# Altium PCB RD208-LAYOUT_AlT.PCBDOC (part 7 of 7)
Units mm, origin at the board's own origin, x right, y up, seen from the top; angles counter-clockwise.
Board outline 240 x 150 mm, 6 copper layers (TOP, Mid-Layer 1, Mid-Layer 2, Mid-Layer 3, Mid-Layer 4, BOTTOM), stack 1.422 mm thick; 773 components, 409 nets, 3936 pads, 97 vias.
Unrouted connection lines stored in the file: 1.
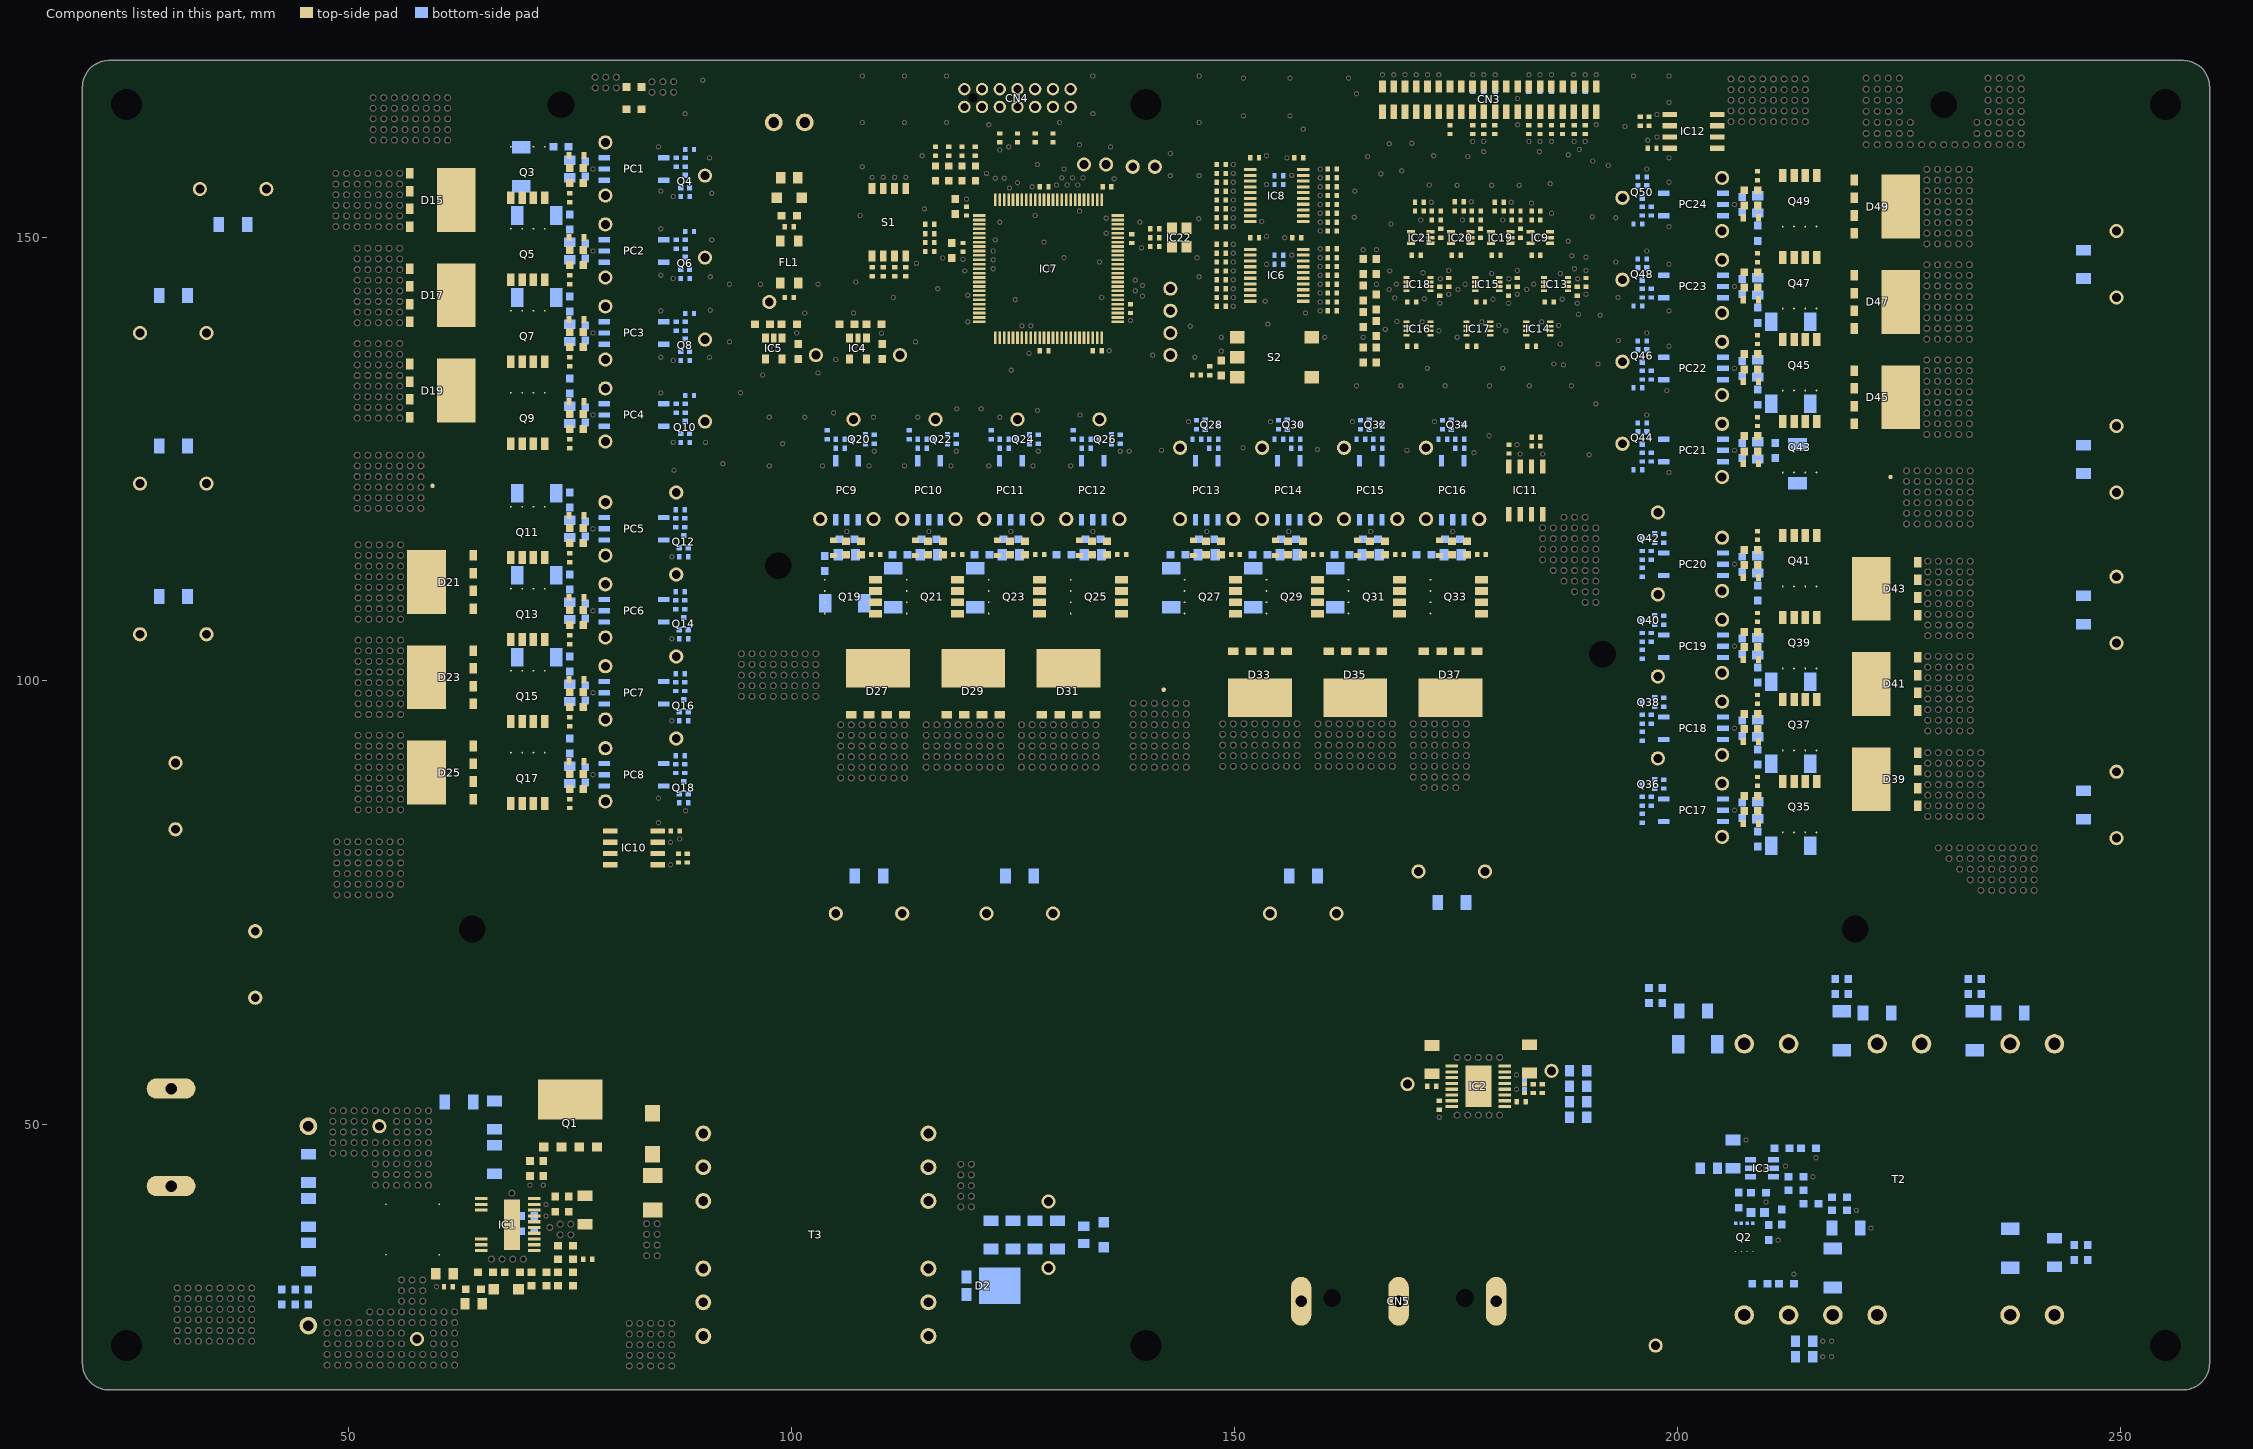
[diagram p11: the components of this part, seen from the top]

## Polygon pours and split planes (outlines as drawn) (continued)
GND on Mid-Layer 2 "MID296" (solid, pour order 69): 218,159.55 cw(c218,160.55) 217,160.55 217,161.35 ccw(c216,161.35) 216,162.35 205.75,162.35 cw(c205.75,162.6) 205.5,162.6 205.5,168.75 cw(c205.75,168.75) 205.75,169 229.988,169 cw(c229.988,168.85) 230,168.999 cw(c230.012,168.85) 230.012,169 240,169 cw(c240,168.85) 240.15,168.85 240.15,160.55 cw(c239.15,160.55) 239.15,159.55
HVU_1_4 on Mid-Layer 2 "MID297" (solid, pour order 70): 37 vertices, not listed, extent 21,85 56.4,138.55
HVW_1_4 on Mid-Layer 2 "MID299" (solid, pour order 72): 25 vertices, not listed, extent 227.6,104.65 252.5,158.15
HVV_1_4 on Mid-Layer 2 "MID2101" (solid, pour order 74): 36 vertices, not listed, extent 125.45,72.75 179,96
HVV_1_4 on Mid-Layer 2 "MID2102" (solid, pour order 75): 170.6,78.35 170.9,78.65 171.7,77.85 171.7,77.65 171.3,77.65
HVV_1_4 on Mid-Layer 2 "MID2103" (solid, pour order 76): 170.9,78.35 170.2,77.65 169.8,77.65 169.8,77.85 170.6,78.65
GND_D on Mid-Layer 2 "MID293" (solid, pour order 66): 134.8,150.35 cw(c134.8,150.45) 134.7,150.45 134.7,151.55 cw(c134.8,151.55) 134.8,151.65 138.4,151.65 cw(c138.4,151.55) 138.5,151.55 138.5,150.45 cw(c138.4,150.45) 138.4,150.35
GND_D on Mid-Layer 2 "MID294" (solid, pour order 67): 24 vertices, not listed, extent 137.45,146.9 146.75,152.6
VP_380R0_INV on Mid-Layer 2 "MID2100" (solid, pour order 73): 104 vertices, not listed, extent 21,34.35 259,169
GND_D on Mid-Layer 2 "MID298" (solid, pour order 71): 427 vertices, not listed, extent 83.75,83.7 199.55,169
VP_3R3_PRH_D on Mid-Layer 3 "MID3104" (solid, pour order 58): 22 vertices, not listed, extent 127.7,135.85 131.3,138.55
GND on Mid-Layer 3 "MID3105" (solid, pour order 59): 22 vertices, not listed, extent 72.6,156.9 81.2,169
GND on Mid-Layer 3 "MID3106" (solid, pour order 60): 217.062,159.5 cw(c217.062,159.65) 216.956,159.544 214.15,162.35 205.75,162.35 cw(c205.75,162.6) 205.5,162.6 205.5,168.75 cw(c205.75,168.75) 205.75,169 229.988,169 cw(c229.988,168.85) 230,168.999 cw(c230.012,168.85) 230.012,169 239.45,169 cw(c239.45,168.85) 239.6,168.85 239.6,159.65 cw(c239.45,159.65) 239.45,159.5
HVU_3_4 on Mid-Layer 3 "MID3107" (solid, pour order 61): 33 vertices, not listed, extent 21,106.3 57.9,159.9
HVV_3_4 on Mid-Layer 3 "MID3108" (solid, pour order 62): 29 vertices, not listed, extent 104.05,71.25 157.5,95.65
HVW_3_4 on Mid-Layer 3 "MID3109" (solid, pour order 63): 25 vertices, not listed, extent 227.6,83.2 252.5,136.65
GND_D on Mid-Layer 3 "MID3110" (solid, pour order 64): 383 vertices, not listed, extent 83.55,78.2 199.55,169
GND on Mid-Layer 3 "MID3111" (solid, pour order 65): 61 vertices, not listed, extent 21,21 249.8,59.4
OUT_V on Mid-Layer 4 "MID4112" (solid, pour order 53): 21 vertices, not listed, extent 137,25.004 173.5,98
OUT_U on Mid-Layer 4 "MID4113" (solid, pour order 54): 42 vertices, not listed, extent 50.55,25 158.65,126.65
OUT_W on Mid-Layer 4 "MID4114" (solid, pour order 55): 42 vertices, not listed, extent 178.35,25 233.5,124.55
GND on Mid-Layer 4 "MID4115" (solid, pour order 56): 217.162,159.5 cw(c217.162,159.65) 217.056,159.544 214.251,162.349 214.25,162.35 205.75,162.35 cw(c205.75,162.6) 205.5,162.6 205.5,168.75 cw(c205.75,168.75) 205.75,169 229.988,169 cw(c229.988,168.85) 230,168.999 cw(c230.012,168.85) 230.012,169 239.6,169 cw(c239.6,168.85) 239.75,168.85 239.75,159.65 cw(c239.6,159.65) 239.6,159.5
GND_D on Mid-Layer 4 "MID4116" (solid, pour order 57): 39 vertices, not listed, extent 83.75,78.2 199.55,169
HVU_3_4 on BOTTOM "BOTTOM117" (solid, pour order 2): 50.95,106.55 cw(c50.95,106.8) 50.7,106.8 50.7,115.5 cw(c50.95,115.5) 50.95,115.75 56.05,115.75 cw(c56.05,115.5) 56.3,115.5 56.3,106.8 cw(c56.05,106.8) 56.05,106.55
HVU_2_4 on BOTTOM "BOTTOM118" (solid, pour order 3): 50.95,95.8 cw(c50.95,96.05) 50.7,96.05 50.7,104.75 cw(c50.95,104.75) 50.95,105 56.05,105 cw(c56.05,104.75) 56.3,104.75 56.3,96.05 cw(c56.05,96.05) 56.05,95.8
HVU_1_4 on BOTTOM "BOTTOM119" (solid, pour order 4): 50.95,85.05 cw(c50.95,85.3) 50.7,85.3 50.7,94 cw(c50.95,94) 50.95,94.25 56.05,94.25 cw(c56.05,94) 56.3,94 56.3,85.3 cw(c56.05,85.3) 56.05,85.05
VP_380R0_INV on BOTTOM "BOTTOM120" (solid, pour order 5): 61.6,160.85 cw(c61.35,160.85) 61.35,160.6 52.65,160.6 cw(c52.65,160.85) 52.4,160.85 52.4,165.95 cw(c52.65,165.95) 52.65,166.2 61.35,166.2 cw(c61.35,165.95) 61.6,165.95
HVV_2_4 on BOTTOM "BOTTOM121" (solid, pour order 6): 159.25,89.95 cw(c159.25,90.2) 159,90.2 159,95.3 cw(c159.25,95.3) 159.25,95.55 167.95,95.55 cw(c167.95,95.3) 168.2,95.3 168.2,90.2 cw(c167.95,90.2) 167.95,89.95
HVV_1_4 on BOTTOM "BOTTOM122" (solid, pour order 7): 171.354,87.5 cw(c171.354,87.75) 171.177,87.573 169.823,88.927 cw(c170,89.104) 169.75,89.104 169.75,95.3 cw(c170,95.3) 170,95.55 176.3,95.55 cw(c176.3,95.3) 176.55,95.3 176.55,89.104 cw(c176.3,89.104) 176.477,88.927 175.123,87.573 cw(c174.946,87.75) 174.946,87.5
HVV_3_4 on BOTTOM "BOTTOM123" (solid, pour order 8): 148.5,89.95 cw(c148.5,90.2) 148.25,90.2 148.25,95.3 cw(c148.5,95.3) 148.5,95.55 157.2,95.55 cw(c157.2,95.3) 157.45,95.3 157.45,90.2 cw(c157.2,90.2) 157.2,89.95
VP_380R0_INV on BOTTOM "BOTTOM124" (solid, pour order 9): 94.2,97.85 cw(c94.2,98.1) 93.95,98.1 93.95,103.2 cw(c94.2,103.2) 94.2,103.45 102.9,103.45 cw(c102.9,103.2) 103.15,103.2 103.15,98.1 cw(c102.9,98.1) 102.9,97.85
N16128748 on BOTTOM "BOTTOM125" (solid, pour order 10): 17 vertices, not listed, extent 114.5,28.75 120.3,34.75
GND on BOTTOM "BOTTOM126" (solid, pour order 11): 115.504,38.5 cw(c115.504,38.75) 115.327,38.573 114.623,39.277 cw(c114.8,39.454) 114.55,39.454 114.55,45.396 cw(c114.8,45.396) 114.623,45.573 114.977,45.927 cw(c115.154,45.75) 115.154,46 134.196,46 cw(c134.196,45.75) 134.373,45.927 135.777,44.523 cw(c135.6,44.346) 135.85,44.346 135.85,38.75 cw(c135.6,38.75) 135.6,38.5
VP_15R0_INV_LDO on BOTTOM "BOTTOM127" (solid, pour order 12): 121.5,28 cw(c121.5,28.25) 121.25,28.25 121.25,36.25 cw(c121.5,36.25) 121.5,36.5 135.65,36.5 cw(c135.65,36.25) 135.9,36.25 135.9,29.612 cw(c135.75,29.612) 135.856,29.506 134.394,28.044 cw(c134.288,28.15) 134.288,28
HVW_1_4 on BOTTOM "BOTTOM128" (solid, pour order 13): 227.95,148.9 cw(c227.95,149.15) 227.7,149.15 227.7,157.85 cw(c227.95,157.85) 227.95,158.1 233.05,158.1 cw(c233.05,157.85) 233.3,157.85 233.3,149.15 cw(c233.05,149.15) 233.05,148.9
HVW_3_4 on BOTTOM "BOTTOM129" (solid, pour order 14): 227.95,127.4 cw(c227.95,127.65) 227.7,127.65 227.7,136.35 cw(c227.95,136.35) 227.95,136.6 233.05,136.6 cw(c233.05,136.35) 233.3,136.35 233.3,127.65 cw(c233.05,127.65) 233.05,127.4
HVW_2_4 on BOTTOM "BOTTOM130" (solid, pour order 15): 227.95,138.15 cw(c227.95,138.4) 227.7,138.4 227.7,147.1 cw(c227.95,147.1) 227.95,147.35 233.05,147.35 cw(c233.05,147.1) 233.3,147.1 233.3,138.4 cw(c233.05,138.4) 233.05,138.15
GND on BOTTOM "BOTTOM131" (solid, pour order 16): 205.85,162.7 cw(c205.85,162.95) 205.6,162.95 205.6,168.05 cw(c205.85,168.05) 205.85,168.3 214.55,168.3 cw(c214.55,168.05) 214.8,168.05 214.8,162.95 cw(c214.55,162.95) 214.55,162.7
GND_D on BOTTOM "BOTTOM132" (solid, pour order 17): 134.344,152.499 cw(c134.414,152.428) 134.485,152.357 134.484,152.356 cw(c134.414,152.427) 134.343,152.498
GND_D on BOTTOM "BOTTOM133" (solid, pour order 18): 39 vertices, not listed, extent 161.45,151.296 184.802,161.1
VP_15R0_INV_LDO on BOTTOM "BOTTOM134" (solid, pour order 19): 185,50 cw(c185,50.25) 184.75,50.25 184.75,52.396 cw(c185,52.396) 184.823,52.573 185.177,52.927 cw(c185.354,52.75) 185.354,53 186.5,53 cw(c186.5,52.75) 186.75,52.75 186.75,50.25 cw(c186.5,50.25) 186.5,50
LDO_15VOUT on BOTTOM "BOTTOM135" (solid, pour order 20): 185.354,53.75 cw(c185.354,54) 185.177,53.823 184.794,54.206 cw(c184.9,54.312) 184.75,54.312 184.75,56.146 cw(c185,56.146) 184.823,56.323 185.256,56.756 cw(c185.362,56.65) 185.362,56.8 186.288,56.8 cw(c186.288,56.65) 186.394,56.756 186.677,56.473 cw(c186.5,56.296) 186.75,56.296 186.75,54 cw(c186.5,54) 186.5,53.75
VP_15R0_INV_ISO on BOTTOM "BOTTOM136" (solid, pour order 21): 190.75,50.25 cw(c190.75,50.5) 190.5,50.5 190.5,56.25 cw(c190.75,56.25) 190.75,56.5 192.25,56.5 cw(c192.25,56.25) 192.5,56.25 192.5,50.5 cw(c192.25,50.5) 192.25,50.25
GND on BOTTOM "BOTTOM137" (solid, pour order 22): 17 vertices, not listed, extent 171,48 184,60
GND on BOTTOM "BOTTOM138" (solid, pour order 23): 48.35,75.25 cw(c48.35,75.35) 48.25,75.35 48.25,82.459 cw(c48.35,82.459) 48.279,82.529 49.221,83.471 cw(c49.291,83.4) 49.291,83.5 56.05,83.5 cw(c56.05,83.25) 56.3,83.25 56.3,75.35 cw(c56.2,75.35) 56.2,75.25
VP_380R0_INV on BOTTOM "BOTTOM139" (solid, pour order 24): 83.5,34.75 cw(c83.5,35) 83.25,35 83.25,38.9 cw(c83.5,38.9) 83.5,39.15 85,39.15 cw(c85,38.9) 85.25,38.9 85.25,35 cw(c85,35) 85,34.75
GND on BOTTOM "BOTTOM140" (solid, pour order 25): 184.6,108.45 cw(c184.6,108.7) 184.35,108.7 184.35,118.65 cw(c184.6,118.65) 184.6,118.9 190.885,118.9 cw(c190.885,118.65) 191.062,118.827 191.249,118.64 cw(c191.143,118.534) 191.282,118.59 cw(c191.05,118.496) 191.3,118.504 191.3,118.499 191.3,108.697 191.3,108.693 cw(c191.05,108.7) 191.05,108.45
GND on BOTTOM "BOTTOM141" (solid, pour order 26): 77.7,166.45 cw(c77.7,166.7) 77.45,166.7 77.45,168.35 cw(c77.7,168.35) 77.7,168.6 80.4,168.6 cw(c80.4,168.35) 80.65,168.35 80.65,166.7 cw(c80.4,166.7) 80.4,166.45
HVV_3_4 on BOTTOM "BOTTOM142" (solid, pour order 27): 105.4,88.65 cw(c105.4,88.9) 105.15,88.9 105.15,95.2 cw(c105.4,95.2) 105.4,95.45 113.1,95.45 cw(c113.1,95.2) 113.35,95.2 113.35,88.9 cw(c113.1,88.9) 113.1,88.65
HVV_2_4 on BOTTOM "BOTTOM143" (solid, pour order 28): 115.05,89.85 cw(c115.05,90.1) 114.8,90.1 114.8,95.2 cw(c115.05,95.2) 115.05,95.45 123.85,95.45 cw(c123.85,95.2) 124.1,95.2 124.1,90.1 cw(c123.85,90.1) 123.85,89.85
HVV_1_4 on BOTTOM "BOTTOM144" (solid, pour order 29): 125.8,89.85 cw(c125.8,90.1) 125.55,90.1 125.55,95.2 cw(c125.8,95.2) 125.8,95.45 134.6,95.45 cw(c134.6,95.2) 134.85,95.2 134.85,90.1 cw(c134.6,90.1) 134.6,89.85
OUT_V on BOTTOM "BOTTOM145" (solid, pour order 30): 138.1,89.75 cw(c138.1,90) 137.85,90 137.85,97.6 cw(c138.1,97.6) 138.1,97.85 145,97.85 cw(c145,97.6) 145.25,97.6 145.25,90 cw(c145,90) 145,89.75
VP_380R0_INV on BOTTOM "BOTTOM146" (solid, pour order 31): 22 vertices, not listed, extent 44.4,42.7 61.05,55
HVU_3_4 on BOTTOM "BOTTOM147" (solid, pour order 32): 48.4,150.65 cw(c48.4,150.9) 48.15,150.9 48.15,157.5 cw(c48.4,157.5) 48.4,157.75 56,157.75 cw(c56,157.5) 56.25,157.5 56.25,150.9 cw(c56,150.9) 56,150.65
HVU_2_4 on BOTTOM "BOTTOM148" (solid, pour order 33): 50.85,139.9 cw(c50.85,140.15) 50.6,140.15 50.6,149 cw(c50.85,149) 50.85,149.25 55.95,149.25 cw(c55.95,149) 56.2,149 56.2,140.15 cw(c55.95,140.15) 55.95,139.9
HVU_1_4 on BOTTOM "BOTTOM149" (solid, pour order 34): 50.85,129.15 cw(c50.85,129.4) 50.6,129.4 50.6,138.3 cw(c50.85,138.3) 50.85,138.55 55.95,138.55 cw(c55.95,138.3) 56.2,138.3 56.2,129.4 cw(c55.95,129.4) 55.95,129.15
OUT_U on BOTTOM "BOTTOM150" (solid, pour order 35): 50.85,118.7 cw(c50.85,118.95) 50.6,118.95 50.6,125.9 cw(c50.85,125.9) 50.85,126.15 58.35,126.15 cw(c58.35,125.9) 58.6,125.9 58.6,118.95 cw(c58.35,118.95) 58.35,118.7
OUT_W on BOTTOM "BOTTOM151" (solid, pour order 36): 225.6,117 cw(c225.6,117.25) 225.35,117.25 225.35,124.15 cw(c225.6,124.15) 225.6,124.4 233.15,124.4 cw(c233.15,124.15) 233.4,124.15 233.4,117.25 cw(c233.15,117.25) 233.15,117
VP_380R0_INV on BOTTOM "BOTTOM152" (solid, pour order 37): 233.926,75.5 cw(c233.926,75.65) 233.82,75.544 227.844,81.52 cw(c227.95,81.626) 227.8,81.626 227.8,82.5 cw(c228.05,82.5) 228.05,82.75 239.946,82.75 cw(c239.946,82.5) 240.123,82.677 240.527,82.273 cw(c240.35,82.096) 240.6,82.096 240.6,75.75 cw(c240.35,75.75) 240.35,75.5
HVW_3_4 on BOTTOM "BOTTOM153" (solid, pour order 38): 228.05,84.3 cw(c228.05,84.55) 227.8,84.55 227.8,92.1 cw(c228.05,92.1) 228.05,92.35 234.35,92.35 cw(c234.35,92.1) 234.6,92.1 234.6,84.55 cw(c234.35,84.55) 234.35,84.3
HVW_2_4 on BOTTOM "BOTTOM154" (solid, pour order 39): 228.05,93.95 cw(c228.05,94.2) 227.8,94.2 227.8,103 cw(c228.05,103) 228.05,103.25 233.15,103.25 cw(c233.15,103) 233.4,103 233.4,94.2 cw(c233.15,94.2) 233.15,93.95
HVW_1_4 on BOTTOM "BOTTOM155" (solid, pour order 40): 228.05,104.65 cw(c228.05,104.9) 227.8,104.9 227.8,113.75 cw(c228.05,113.75) 228.05,114 233.15,114 cw(c233.15,113.75) 233.4,113.75 233.4,104.9 cw(c233.15,104.9) 233.15,104.65
N3161846 on BOTTOM "BOTTOM156" (solid, pour order 41): 206.6,38.6 cw(c206.6,38.85) 206.35,38.85 206.35,40.25 cw(c206.6,40.25) 206.6,40.5 208.5,40.5 cw(c208.5,40.25) 208.75,40.25 208.75,39.75 cw(c208.5,39.75) 208.5,39.5 208.25,39.5 ccw(c208.25,39.25) 208,39.25 208,38.85 cw(c207.75,38.85) 207.75,38.6
TRANS2_PRI on BOTTOM "BOTTOM157" (solid, pour order 42): 207.104,27.25 cw(c207.104,27.5) 206.927,27.323 206.323,27.927 cw(c206.5,28.104) 206.25,28.104 206.25,37.75 cw(c206.5,37.75) 206.5,38 208.5,38 cw(c208.5,37.75) 208.75,37.75 208.75,28.104 cw(c208.5,28.104) 208.677,27.927 208.073,27.323 cw(c207.896,27.5) 207.896,27.25
GND_D on BOTTOM "BOTTOM158" (solid, pour order 43): 38 vertices, not listed, extent 84.45,78.2 89.05,87.58
GND_D on BOTTOM "BOTTOM159" (solid, pour order 44): 37 vertices, not listed, extent 83.75,158.3 91.45,168.55
GND_D on BOTTOM "BOTTOM160" (solid, pour order 45): 40 vertices, not listed, extent 84.45,149.05 91.45,155.95
GND_D on BOTTOM "BOTTOM161" (solid, pour order 46): 40 vertices, not listed, extent 84.45,139.8 91.45,146.7
GND on BOTTOM "BOTTOM162" (solid, pour order 47): 79 vertices, not listed, extent 21,21 88.15,47.1
GND_D on BOTTOM "BOTTOM163" (solid, pour order 48): 770 vertices, not listed, extent 92.15,121.231 199.55,169
VP_15R0_INV_ISO on BOTTOM "BOTTOM164" (solid, pour order 49): 198.5,23 cw(c198.5,24) 197.793,23.293 196.793,24.293 cw(c197.5,25) 198.207,25.707 198.914,25 211.15,25 211.5,25.35 211.5,28.45 cw(c212.5,28.45) 213.5,28.45 213.5,23.491 cw(c213.4,23.491) 213.471,23.421 213.079,23.029 cw(c213.009,23.1) 213.009,23
GND on BOTTOM "BOTTOM165" (solid, pour order 50): 216.15,23.45 cw(c216.15,23.55) 216.05,23.55 216.05,25.7 cw(c216.15,25.7) 216.15,25.8 217.55,25.8 cw(c217.55,25.7) 217.65,25.7 217.65,23.55 cw(c217.55,23.55) 217.55,23.45
GND_D on BOTTOM "BOTTOM166" (solid, pour order 51): 80 vertices, not listed, extent 84.45,122.1 95.955,137.45
GND on BOTTOM "BOTTOM167" (solid, pour order 52): 217.15,159.5 cw(c217.15,159.65) 217,159.65 217,162.35 205.75,162.35 cw(c205.75,162.6) 205.5,162.6 205.5,168.75 cw(c205.75,168.75) 205.75,169 229.988,169 cw(c229.988,168.85) 230,168.999 cw(c230.012,168.85) 230.012,169 239.6,169 cw(c239.6,168.85) 239.75,168.85 239.75,159.65 cw(c239.6,159.65) 239.6,159.5
no net on Top Solder "TOPSOLDER168" (solid, pour order 0): 175,36.75 cw(c176,36.75) 177,36.75 177,24 cw(c176,24) 175,24
no net on Top Solder "TOPSOLDER169" (solid, pour order 0): 160,36.75 cw(c161,36.75) 162,36.75 162,24 cw(c161,24) 160,24
no net on Bottom Solder "BOTTOMSOLDER170" (solid, pour order 0): 160,36.75 cw(c161,36.75) 162,36.75 162,24 cw(c161,24) 160,24
no net on Bottom Solder "BOTTOMSOLDER171" (solid, pour order 0): 175,36.75 cw(c176,36.75) 177,36.75 177,24 cw(c176,24) 175,24

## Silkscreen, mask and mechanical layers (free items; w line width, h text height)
Top Overlay:
  drawing of 409 lines, arcs and shapes, not listed
  text "GND D" at 118.5,132.5 h0.61
  text "MULTI-LEVEL INVERTER" at 121.35,61.55 h3
  text "1" at 63.6,41.6 h0.61
  text "W" at 179.25,40.15 h2.41
  text "U" at 157.45,40 h2.41
  text "V" at 168.25,40 h2.41
Bottom Overlay:
  drawing of 320 lines, arcs and shapes, not listed
Top Paste:
  rectangle: 57.65,34.15 62.85,36.1
  rectangle: 57.65,40.1 62.85,42.05
  rectangle: 51.65,34.15 56.85,36.1
Top Solder:
  rectangle: 57.6,34.1 62.9,36.15
  rectangle: 51.6,34.1 56.9,36.15
  rectangle: 57.6,40.05 62.9,42.1
  rectangle: 51.6,40.05 56.9,42.1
